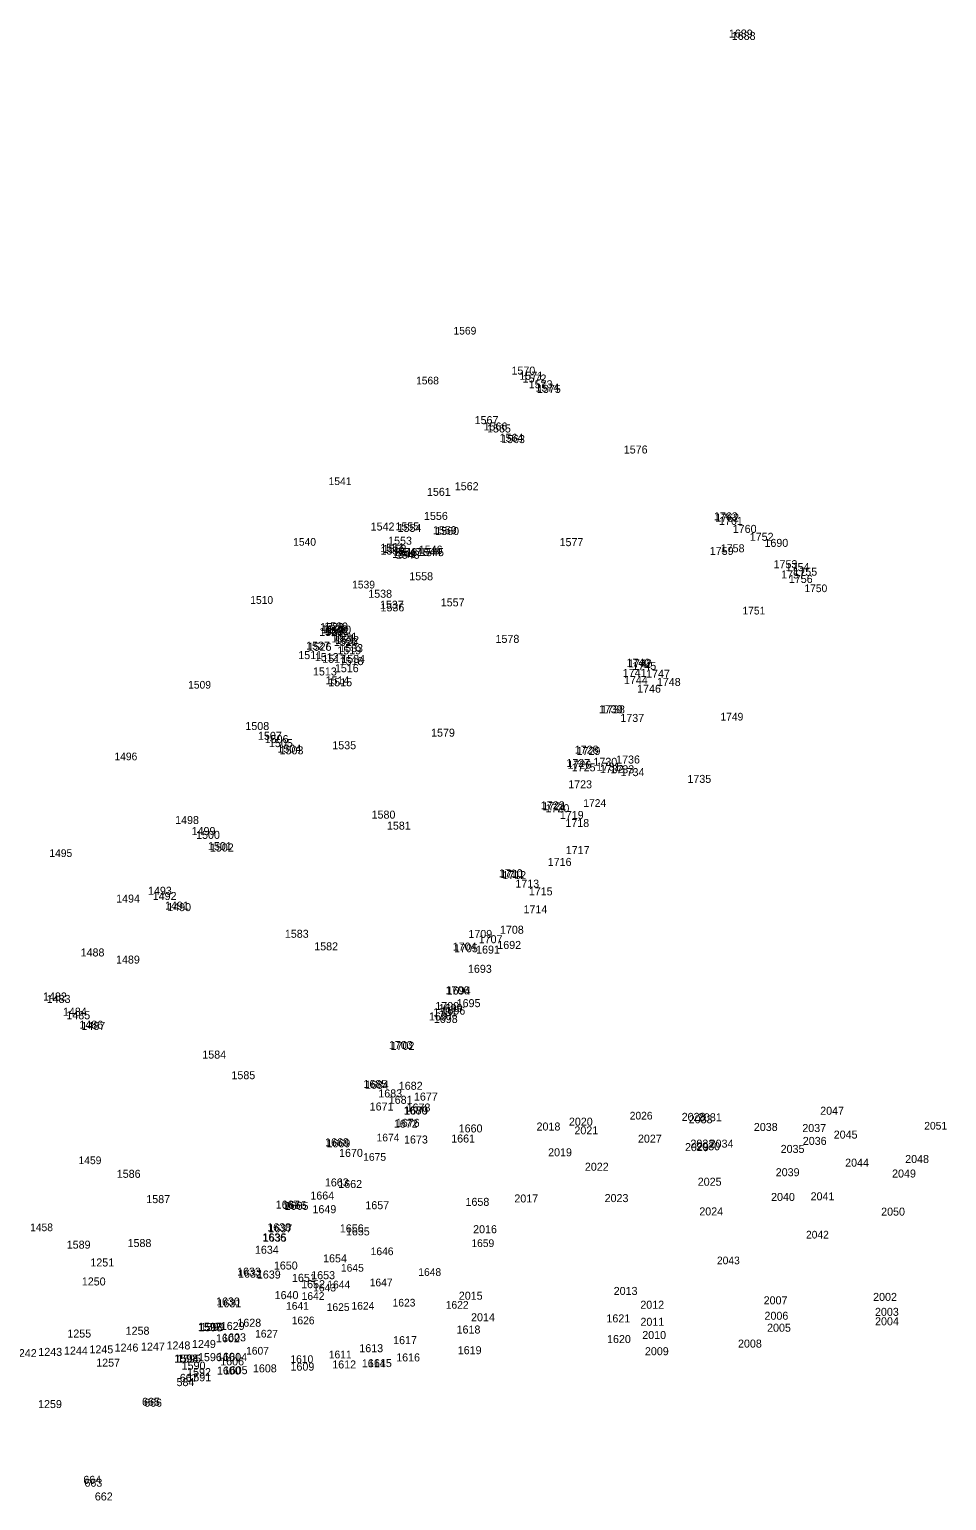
# Model space of a CAD drawing. Extents: x 359002 to 1164845, y 1141798 to 1525369.
# Drawn here: x 360220 to 360506.7, y 1524795.7 to 1525255.4 of the extents above; entities that cross this region are included whole.
import ezdxf

# ---------------------------------------------------------------- set-up
doc = ezdxf.new("R2010")
doc.units = 0
for name, color, linetype in [('BSUBM_I', 7, 'Continuous'), ('BVC_I', 7, 'Continuous'), ('BWW_I', 7, 'Continuous'), ('CPBM_I', 7, 'Continuous'), ('DS_I', 7, 'Continuous'), ('LABL_I', 7, 'Continuous'), ('LBC_I', 7, 'Continuous'), ('LBF_I', 7, 'Continuous'), ('LELB_I', 7, 'Continuous'), ('LELS_I', 7, 'Continuous'), ('LMB_I', 7, 'Continuous'), ('LPST_I', 7, 'Continuous'), ('LS_I', 7, 'Continuous'), ('LSHC_I', 7, 'Continuous'), ('LSHD_I', 7, 'Continuous'), ('LTD_I', 7, 'Continuous'), ('LUKP_I', 7, 'Continuous'), ('PE_I', 7, 'Continuous'), ('PELB_I', 7, 'Continuous'), ('PRC_I', 7, 'Continuous'), ('RC_I', 7, 'Continuous'), ('RCD_I', 7, 'Continuous'), ('RDP_I', 7, 'Continuous'), ('RGW_I', 7, 'Continuous'), ('RSW_I', 7, 'Continuous'), ('S_I', 7, 'Continuous'), ('SDEL_I', 7, 'Continuous'), ('UEMH_I', 7, 'Continuous'), ('UEO_I', 7, 'Continuous'), ('UG_I', 7, 'Continuous'), ('UGV_I', 7, 'Continuous'), ('UPGW_I', 7, 'Continuous'), ('UPL_I', 7, 'Continuous'), ('USMH_I', 7, 'Continuous'), ('UTMH_I', 7, 'Continuous'), ('UUMH_I', 7, 'Continuous'), ('UWV_I', 7, 'Continuous')]:
    doc.layers.add(name, color=color, linetype=linetype)

msp = doc.modelspace()

# ---------------------------------------------------------------- texts
at = {"layer": 'BSUBM_I'}
for s, p in [('667', (360267, 1524832.76)), ('1591', (360269.37, 1524832.93)), ('662', (360240.45, 1524795.7))]:
    msp.add_text(s, height=2.501, dxfattribs=at).set_placement(p)
at = {"layer": 'BVC_I'}
msp.add_text('584', height=2.501, dxfattribs=at).set_placement((360265.98, 1524831.43))
at = {"layer": 'BWW_I'}
for s, p in [('1602', (360278.31, 1524845.13)), ('1603', (360280.25, 1524845.42)), ('1601', (360278.63, 1524839.36)), ('1604', (360280.6, 1524839.24)), ('1605', (360280.75, 1524835.16)), ('1600', (360278.62, 1524835.04))]:
    msp.add_text(s, height=2.501, dxfattribs=at).set_placement(p)
at = {"layer": 'CPBM_I'}
msp.add_text('1688', height=2.501, dxfattribs=at).set_placement((360439.51, 1525252.14))
at = {"layer": 'DS_I'}
msp.add_text('1667', height=2.501, dxfattribs=at).set_placement((360296.98, 1524886.91))
at = {"layer": 'LABL_I'}
for s, p in [('2018', (360378.51, 1524911.31)), ('2045', (360471.39, 1524908.78)), ('2019', (360382.12, 1524903.25)), ('2019', (360382.12, 1524903.25)), ('2049', (360489.63, 1524896.62)), ('2017', (360371.57, 1524888.83)), ('2016', (360358.68, 1524879.21)), ('2015', (360354.21, 1524858.43)), ('2012', (360410.94, 1524855.61)), ('2007', (360449.49, 1524856.99)), ('2002', (360483.7, 1524858.06)), ('2014', (360358.04, 1524851.7))]:
    msp.add_text(s, height=2.501, dxfattribs=at).set_placement(p)
at = {"layer": 'LBC_I'}
for s, p in [('1734', (360404.79, 1525022.06)), ('1735', (360425.66, 1525019.94)), ('1717', (360387.64, 1524997.71)), ('1714', (360374.42, 1524979.19)), ('1695', (360353.54, 1524949.86)), ('1682', (360335.45, 1524924.04)), ('1677', (360340.19, 1524920.66)), ('1660', (360354.17, 1524910.71)), ('1649', (360308.47, 1524885.47)), ('1656', (360317.03, 1524879.47)), ('1650', (360296.41, 1524867.87)), ('1654', (360311.79, 1524870.11)), ('1651', (360302.06, 1524864.02)), ('1653', (360308.08, 1524864.85)), ('1652', (360304.93, 1524862.04))]:
    msp.add_text(s, height=2.501, dxfattribs=at).set_placement(p)
at = {"layer": 'LBF_I'}
for s, p in [('1682', (360335.45, 1524924.04)), ('1681', (360332.31, 1524919.65)), ('1677', (360340.19, 1524920.66)), ('1680', (360336.97, 1524916.34)), ('1679', (360337.15, 1524916.28)), ('1678', (360337.89, 1524917.24))]:
    msp.add_text(s, height=2.501, dxfattribs=at).set_placement(p)
at = {"layer": 'LELB_I'}
for s, p in [('1571', (360373.14, 1525145.91)), ('1566', (360361.94, 1525130.07)), ('1556', (360343.33, 1525102.12)), ('1525', (360310.57, 1525065.87)), ('1512', (360309.2, 1525058)), ('1507', (360291.45, 1525033.41)), ('1499', (360270.7, 1525003.64)), ('1494', (360247.11, 1524982.55)), ('1493', (360257.07, 1524984.98)), ('1488', (360236.01, 1524965.71)), ('1483', (360225.41, 1524951.18)), ('1484', (360230.48, 1524947.18)), ('1679', (360337.15, 1524916.28)), ('1672', (360333.91, 1524912.2)), ('1676', (360334.52, 1524912.47)), ('2018', (360378.51, 1524911.31)), ('2020', (360388.62, 1524912.83)), ('2021', (360390.34, 1524910.11)), ('2038', (360446.42, 1524911.17)), ('2037', (360461.57, 1524910.83)), ('2045', (360471.39, 1524908.78)), ('1673', (360337.09, 1524907.25)), ('2027', (360410.2, 1524907.52)), ('2029', (360424.9, 1524904.87)), ('2030', (360428.43, 1524905.13)), ('2034', (360432.61, 1524905.96)), ('2035', (360454.8, 1524904.31)), ('2036', (360461.72, 1524906.81)), ('2019', (360382.12, 1524903.25)), ('2044', (360474.95, 1524900.01)), ('2022', (360393.61, 1524898.74)), ('2039', (360453.26, 1524897.02)), ('2025', (360428.89, 1524894.06)), ('1657', (360325, 1524886.72)), ('1658', (360356.3, 1524887.77)), ('2017', (360371.57, 1524888.83)), ('2023', (360399.78, 1524888.94)), ('2040', (360451.81, 1524889.3)), ('2041', (360464.16, 1524889.5)), ('2024', (360429.38, 1524884.78)), ('2050', (360486.21, 1524884.71)), ('1655', (360318.92, 1524878.53)), ('1654', (360311.79, 1524870.11)), ('1651', (360302.06, 1524864.02)), ('1640', (360296.65, 1524858.62)), ('1628', (360285, 1524849.99)), ('1621', (360400.34, 1524851.35)), ('2011', (360410.98, 1524850.29)), ('2011', (360410.98, 1524850.29)), ('2006', (360449.75, 1524852.17)), ('2003', (360484.28, 1524853.39)), ('2004', (360484.31, 1524850.44)), ('1598', (360272.85, 1524848.57)), ('1617', (360333.68, 1524844.55)), ('1618', (360353.52, 1524847.87)), ('1620', (360400.54, 1524844.89)), ('2010', (360411.54, 1524846.15)), ('2010', (360411.54, 1524846.15)), ('2005', (360450.56, 1524848.43)), ('1613', (360323.11, 1524842.03)), ('1619', (360353.88, 1524841.4)), ('1594', (360265.44, 1524838.8)), ('1605', (360280.75, 1524835.16)), ('1608', (360289.86, 1524835.73)), ('1609', (360301.61, 1524836.27)), ('1612', (360314.65, 1524836.95)), ('1612', (360314.65, 1524836.95)), ('1614', (360323.9, 1524837.31)), ('1615', (360325.83, 1524837.38)), ('1616', (360334.64, 1524839.15)), ('1592', (360269.29, 1524834.56)), ('1591', (360269.37, 1524832.93)), ('1600', (360278.62, 1524835.04))]:
    msp.add_text(s, height=2.501, dxfattribs=at).set_placement(p)
at = {"layer": 'LELS_I'}
for s, p in [('1569', (360352.55, 1525160.06)), ('1568', (360340.85, 1525144.48)), ('1541', (360313.51, 1525113.02)), ('1540', (360302.44, 1525094.06)), ('1539', (360320.87, 1525080.71)), ('1750', (360462.23, 1525079.56)), ('1510', (360289.03, 1525075.9)), ('1751', (360442.87, 1525072.57)), ('1509', (360269.61, 1525049.41)), ('1749', (360435.99, 1525039.44)), ('1496', (360246.58, 1525027.01)), ('1724', (360393.12, 1525012.45)), ('1495', (360226.24, 1524996.8)), ('2026', (360407.63, 1524914.75)), ('2051', (360499.68, 1524911.6)), ('1674', (360328.51, 1524907.91)), ('1459', (360235.36, 1524900.8)), ('1675', (360324.33, 1524901.85)), ('1458', (360220.22, 1524879.85)), ('2042', (360462.72, 1524877.56)), ('1646', (360326.66, 1524872.36)), ('1659', (360358.14, 1524874.9)), ('2043', (360434.89, 1524869.51)), ('1645', (360317.37, 1524867.2)), ('1648', (360341.55, 1524865.88)), ('1642', (360305.08, 1524858.38)), ('1643', (360308.68, 1524861.02)), ('1644', (360313.11, 1524861.97)), ('1647', (360326.37, 1524862.62)), ('1641', (360300.21, 1524855.29)), ('1625', (360312.92, 1524854.93)), ('1624', (360320.67, 1524855.33)), ('1623', (360333.51, 1524856.31)), ('1622', (360350.13, 1524855.63)), ('1626', (360301.99, 1524850.76)), ('1627', (360290.55, 1524846.62)), ('1607', (360287.73, 1524841.28)), ('1611', (360313.58, 1524840.11)), ('1610', (360301.58, 1524838.67))]:
    msp.add_text(s, height=2.4, dxfattribs=at).set_placement(p)
at = {"layer": 'LMB_I'}
msp.add_text('1561', height=2.501, dxfattribs=at).set_placement((360344.25, 1525109.65))
at = {"layer": 'LPST_I'}
for s, p in [('1753', (360452.58, 1525087.04)), ('2033', (360426.06, 1524913.56)), ('2032', (360426.6, 1524905.97))]:
    msp.add_text(s, height=2.501, dxfattribs=at).set_placement(p)
at = {"layer": 'LS_I'}
for s, p in [('1757', (360454.95, 1525083.83)), ('1754', (360456.36, 1525086.14)), ('1755', (360458.77, 1525084.7)), ('1756', (360457.36, 1525082.42)), ('2028', (360423.87, 1524914.33)), ('2031', (360428.96, 1524914.2)), ('2029', (360424.9, 1524904.87)), ('2030', (360428.43, 1524905.13)), ('1629', (360279.81, 1524848.99)), ('1629', (360279.81, 1524848.99)), ('1255', (360231.86, 1524846.61)), ('1258', (360250.08, 1524847.49)), ('1597', (360272.65, 1524848.71)), ('1598', (360272.85, 1524848.57)), ('1599', (360273.48, 1524848.68)), ('1603', (360280.25, 1524845.42)), ('1257', (360240.88, 1524837.51)), ('1593', (360265.28, 1524838.8)), ('1594', (360265.44, 1524838.8)), ('1595', (360266.2, 1524838.77)), ('1596', (360272.7, 1524839.23))]:
    msp.add_text(s, height=2.501, dxfattribs=at).set_placement(p)
at = {"layer": 'LSHC_I'}
for s, p in [('1716', (360382, 1524993.99)), ('1715', (360376.09, 1524984.8)), ('1693', (360357.07, 1524960.59)), ('1696', (360348.8, 1524947.53))]:
    msp.add_text(s, height=2.501, dxfattribs=at).set_placement(p)
at = {"layer": 'LSHD_I'}
msp.add_text('1708', height=2.501, dxfattribs=at).set_placement((360367.07, 1524972.8))
at = {"layer": 'LTD_I'}
msp.add_text('1662', height=2.501, dxfattribs=at).set_placement((360316.54, 1524893.34))
at = {"layer": 'LUKP_I'}
for s, p in [('1692', (360366.24, 1524968.05)), ('1701', (360346.21, 1524947.03)), ('1242', (360214.84, 1524840.48)), ('1243', (360222.79, 1524840.88)), ('1244', (360230.81, 1524841.27)), ('1245', (360238.77, 1524841.67)), ('1246', (360246.63, 1524842.22)), ('1247', (360254.88, 1524842.53)), ('1248', (360262.86, 1524842.89)), ('1249', (360270.82, 1524843.36)), ('1606', (360279.64, 1524837.91))]:
    msp.add_text(s, height=2.501, dxfattribs=at).set_placement(p)
at = {"layer": 'PE_I'}
for s, p in [('1575', (360378.64, 1525141.81)), ('1563', (360367.44, 1525126.13)), ('1763', (360433.94, 1525101.99)), ('1560', (360346.84, 1525097.4)), ('1545', (360342.13, 1525090.81)), ('1536', (360329.73, 1525073.54)), ('1740', (360406.61, 1525056.24)), ('1515', (360313.42, 1525050.14)), ('1739', (360397.99, 1525041.71)), ('1503', (360298.2, 1525028.87)), ('1728', (360390.46, 1525029.08)), ('1727', (360387.82, 1525024.91)), ('1722', (360379.83, 1525011.68)), ('1502', (360276.42, 1524998.5)), ('1710', (360366.75, 1524990.47)), ('1490', (360263.08, 1524979.87)), ('1704', (360352.31, 1524967.54)), ('1487', (360236.25, 1524942.76)), ('1703', (360332.36, 1524936.77)), ('1685', (360324.4, 1524924.61)), ('1668', (360312.4, 1524906.39)), ('1666', (360299.17, 1524886.8)), ('1638', (360294.34, 1524879.82)), ('1633', (360284.9, 1524865.96)), ('1630', (360278.33, 1524856.63)), ('1630', (360278.33, 1524856.63)), ('1597', (360272.65, 1524848.71)), ('1593', (360265.28, 1524838.8)), ('665', (360255.18, 1524825.3)), ('664', (360236.84, 1524800.9))]:
    msp.add_text(s, height=2.501, dxfattribs=at).set_placement(p)
at = {"layer": 'PELB_I'}
for s, p in [('1752', (360445.14, 1525095.6)), ('1748', (360416.11, 1525050.24)), ('1579', (360345.54, 1525034.39)), ('1736', (360403.38, 1525026)), ('1581', (360331.74, 1525005.33)), ('1582', (360309.02, 1524967.61)), ('1585', (360283.15, 1524927.35)), ('1587', (360256.53, 1524888.62)), ('1588', (360250.68, 1524874.89)), ('1588', (360250.68, 1524874.89)), ('1255', (360231.86, 1524846.61))]:
    msp.add_text(s, height=2.501, dxfattribs=at).set_placement(p)
at = {"layer": 'PRC_I'}
for s, p in [('1576', (360405.77, 1525122.88)), ('1577', (360385.69, 1525093.93)), ('1578', (360365.68, 1525063.7)), ('1579', (360345.54, 1525034.39)), ('1580', (360326.95, 1525008.78)), ('1583', (360299.84, 1524971.54)), ('1584', (360274.04, 1524933.79)), ('1586', (360247.31, 1524896.53)), ('1589', (360231.67, 1524874.39)), ('1589', (360231.67, 1524874.39))]:
    msp.add_text(s, height=2.501, dxfattribs=at).set_placement(p)
at = {"layer": 'RC_I'}
for s, p in [('1574', (360378.15, 1525142.23)), ('1564', (360366.95, 1525126.55)), ('1555', (360334.4, 1525098.86)), ('1554', (360335.07, 1525098.38)), ('1559', (360346.1, 1525097.67)), ('1762', (360434.35, 1525101.57)), ('1553', (360332.12, 1525094.37)), ('1552', (360330.38, 1525091.82)), ('1548', (360333.78, 1525090.8)), ('1547', (360335.15, 1525090.81)), ('1525', (360310.57, 1525065.87)), ('1524', (360311.37, 1525066.71)), ('1523', (360311.91, 1525066.69)), ('1522', (360312.42, 1525066.16)), ('1527', (360306.48, 1525061.58)), ('1526', (360306.98, 1525061.23)), ('1742', (360407.1, 1525056.04)), ('1514', (360312.57, 1525050.74)), ('1504', (360297.53, 1525029.39)), ('1726', (360388.17, 1525024.37)), ('1721', (360380.34, 1525011.39)), ('1501', (360275.8, 1524998.93)), ('1711', (360367.2, 1524990.2)), ('1491', (360262.39, 1524980.35)), ('1705', (360352.72, 1524967.02)), ('1486', (360235.61, 1524943.13)), ('1702', (360332.88, 1524936.52)), ('1684', (360324.85, 1524924.35)), ('1669', (360312.84, 1524906.06)), ('1665', (360299.76, 1524886.52)), ('1636', (360292.81, 1524876.68)), ('1635', (360292.96, 1524876.56)), ('1637', (360294.69, 1524879.49)), ('1634', (360290.49, 1524872.8)), ('1632', (360285.21, 1524865.32)), ('1631', (360278.76, 1524856.06)), ('1599', (360273.48, 1524848.68)), ('1595', (360266.2, 1524838.77)), ('666', (360255.85, 1524824.99)), ('663', (360237.2, 1524799.99))]:
    msp.add_text(s, height=2.501, dxfattribs=at).set_placement(p)
at = {"layer": 'RCD_I'}
for s, p in [('1559', (360346.1, 1525097.67)), ('1543', (360334.53, 1525089.99)), ('1547', (360335.15, 1525090.81)), ('1544', (360341.29, 1525090.86)), ('1544', (360341.29, 1525090.86)), ('1546', (360341.7, 1525091.6)), ('1546', (360341.7, 1525091.6)), ('1537', (360329.56, 1525074.36)), ('1522', (360312.42, 1525066.16)), ('1521', (360314.43, 1525063.82)), ('1520', (360315.14, 1525062.74)), ('1532', (360315.58, 1525063.35)), ('1533', (360316.81, 1525060.81)), ('1519', (360316.25, 1525060.12)), ('1518', (360316.97, 1525056.75)), ('1518', (360316.97, 1525056.75)), ('1534', (360317.49, 1525057.44)), ('1534', (360317.49, 1525057.44)), ('1742', (360407.1, 1525056.04)), ('1516', (360315.47, 1525054.54)), ('1741', (360405.44, 1525053.08)), ('1514', (360312.57, 1525050.74)), ('1738', (360398.69, 1525041.66)), ('1729', (360391.02, 1525028.66)), ('1726', (360388.17, 1525024.37))]:
    msp.add_text(s, height=2.501, dxfattribs=at).set_placement(p)
at = {"layer": 'RDP_I'}
for s, p in [('1570', (360370.67, 1525147.53)), ('1567', (360359.15, 1525132.06)), ('1555', (360334.4, 1525098.86)), ('1551', (360329.65, 1525092.17)), ('1550', (360329.74, 1525091.29)), ('1549', (360333.38, 1525090.22)), ('1543', (360334.53, 1525089.99)), ('1528', (360310.85, 1525067.37)), ('1529', (360312.14, 1525067.57)), ('1530', (360313.11, 1525066.59)), ('1527', (360306.48, 1525061.58)), ('1531', (360315, 1525064.34)), ('1532', (360315.58, 1525063.35)), ('1511', (360304.04, 1525058.63)), ('1742', (360407.1, 1525056.04)), ('1745', (360408.48, 1525055.26)), ('1508', (360287.5, 1525036.47)), ('1726', (360388.17, 1525024.37)), ('1730', (360396.29, 1525025.28)), ('1731', (360397.24, 1525023.75)), ('1725', (360389.5, 1525023.55)), ('1732', (360398.3, 1525023.02)), ('1733', (360401.59, 1525022.95)), ('1734', (360404.79, 1525022.06)), ('1498', (360265.55, 1525007.09)), ('1494', (360247.11, 1524982.55)), ('1482', (360224.26, 1524951.94)), ('2047', (360467.16, 1524916.24)), ('2048', (360493.72, 1524901.15))]:
    msp.add_text(s, height=2.501, dxfattribs=at).set_placement(p)
at = {"layer": 'RGW_I'}
msp.add_text('2009', height=2.501, dxfattribs=at).set_placement((360412.38, 1524841.09))
at = {"layer": 'RSW_I'}
for s, p in [('1572', (360374.16, 1525145.06)), ('1565', (360363.04, 1525129.45)), ('1556', (360343.33, 1525102.12)), ('1761', (360435.52, 1525100.56)), ('1760', (360439.83, 1525098.07)), ('1543', (360334.53, 1525089.99)), ('1547', (360335.15, 1525090.81)), ('1758', (360436.07, 1525092.01)), ('1538', (360325.9, 1525077.8)), ('1520', (360315.14, 1525062.74)), ('1532', (360315.58, 1525063.35)), ('1517', (360311.52, 1525057.47)), ('1513', (360308.62, 1525053.52)), ('1745', (360408.48, 1525055.26)), ('1747', (360412.74, 1525052.82)), ('1744', (360405.83, 1525050.83)), ('1746', (360409.94, 1525048.14)), ('1737', (360404.7, 1525039)), ('1506', (360293.54, 1525032.38)), ('1730', (360396.29, 1525025.28)), ('1725', (360389.5, 1525023.55)), ('1720', (360381.3, 1525010.77)), ('1719', (360385.79, 1525008.67)), ('1500', (360272.1, 1525002.45)), ('1711', (360367.2, 1524990.2)), ('1712', (360367.82, 1524989.86)), ('1713', (360371.88, 1524987.21)), ('1492', (360258.54, 1524983.34)), ('1707', (360360.42, 1524969.84)), ('1706', (360350.07, 1524953.87)), ('1485', (360231.56, 1524946.08)), ('1697', (360344.89, 1524945.7)), ('1700', (360346.85, 1524948.98)), ('1699', (360347.92, 1524948.33)), ('1698', (360346.41, 1524944.92)), ('1683', (360329.05, 1524921.65)), ('1681', (360332.31, 1524919.65)), ('1671', (360326.35, 1524917.56)), ('1680', (360336.97, 1524916.34)), ('1678', (360337.89, 1524917.24)), ('1672', (360333.91, 1524912.2)), ('1660', (360354.17, 1524910.71)), ('1661', (360351.83, 1524907.55)), ('1670', (360316.78, 1524903.07)), ('1664', (360307.81, 1524889.73)), ('1639', (360291.1, 1524865.05)), ('1629', (360279.81, 1524848.99)), ('1596', (360272.7, 1524839.23)), ('1601', (360278.63, 1524839.36)), ('1592', (360269.29, 1524834.56))]:
    msp.add_text(s, height=2.501, dxfattribs=at).set_placement(p)
at = {"layer": 'S_I'}
for s, p in [('1718', (360387.51, 1525006.16)), ('1663', (360312.35, 1524893.84))]:
    msp.add_text(s, height=2.501, dxfattribs=at).set_placement(p)
at = {"layer": 'SDEL_I'}
msp.add_text('2008', height=2.501, dxfattribs=at).set_placement((360441.47, 1524843.47))
at = {"layer": 'UEMH_I'}
msp.add_text('1590', height=2.501, dxfattribs=at).set_placement((360267.59, 1524836.58))
at = {"layer": 'UEO_I'}
for s, p in [('1690', (360449.73, 1525093.7)), ('1691', (360359.61, 1524966.6))]:
    msp.add_text(s, height=2.501, dxfattribs=at).set_placement(p)
at = {"layer": 'UG_I'}
for s, p in [('1573', (360376.06, 1525143.27)), ('1562', (360352.95, 1525111.41)), ('1759', (360432.65, 1525091.19)), ('1505', (360294.88, 1525031.12)), ('1723', (360388.4, 1525018.25)), ('1709', (360357.2, 1524971.49)), ('1489', (360247.07, 1524963.48))]:
    msp.add_text(s, height=2.501, dxfattribs=at).set_placement(p)
at = {"layer": 'UGV_I'}
msp.add_text('1505', height=2.501, dxfattribs=at).set_placement((360294.88, 1525031.12))
at = {"layer": 'UPGW_I'}
for s, p in [('1694', (360350.43, 1524953.8)), ('2013', (360402.62, 1524859.93))]:
    msp.add_text(s, height=2.501, dxfattribs=at).set_placement(p)
at = {"layer": 'UPL_I'}
msp.add_text('1691', height=2.501, dxfattribs=at).set_placement((360359.61, 1524966.6))
at = {"layer": 'USMH_I'}
for s, p in [('1689', (360438.61, 1525252.87)), ('1542', (360326.66, 1525098.81))]:
    msp.add_text(s, height=2.501, dxfattribs=at).set_placement(p)
at = {"layer": 'UTMH_I'}
for s, p in [('1251', (360239.05, 1524868.82)), ('1250', (360236.38, 1524862.89))]:
    msp.add_text(s, height=2.501, dxfattribs=at).set_placement(p)
at = {"layer": 'UUMH_I'}
msp.add_text('1259', height=2.501, dxfattribs=at).set_placement((360222.71, 1524824.57))
at = {"layer": 'UWV_I'}
for s, p in [('1558', (360338.72, 1525083.26)), ('1557', (360348.57, 1525075.11)), ('1535', (360314.67, 1525030.46))]:
    msp.add_text(s, height=2.501, dxfattribs=at).set_placement(p)

doc.saveas('drawing.dxf')
